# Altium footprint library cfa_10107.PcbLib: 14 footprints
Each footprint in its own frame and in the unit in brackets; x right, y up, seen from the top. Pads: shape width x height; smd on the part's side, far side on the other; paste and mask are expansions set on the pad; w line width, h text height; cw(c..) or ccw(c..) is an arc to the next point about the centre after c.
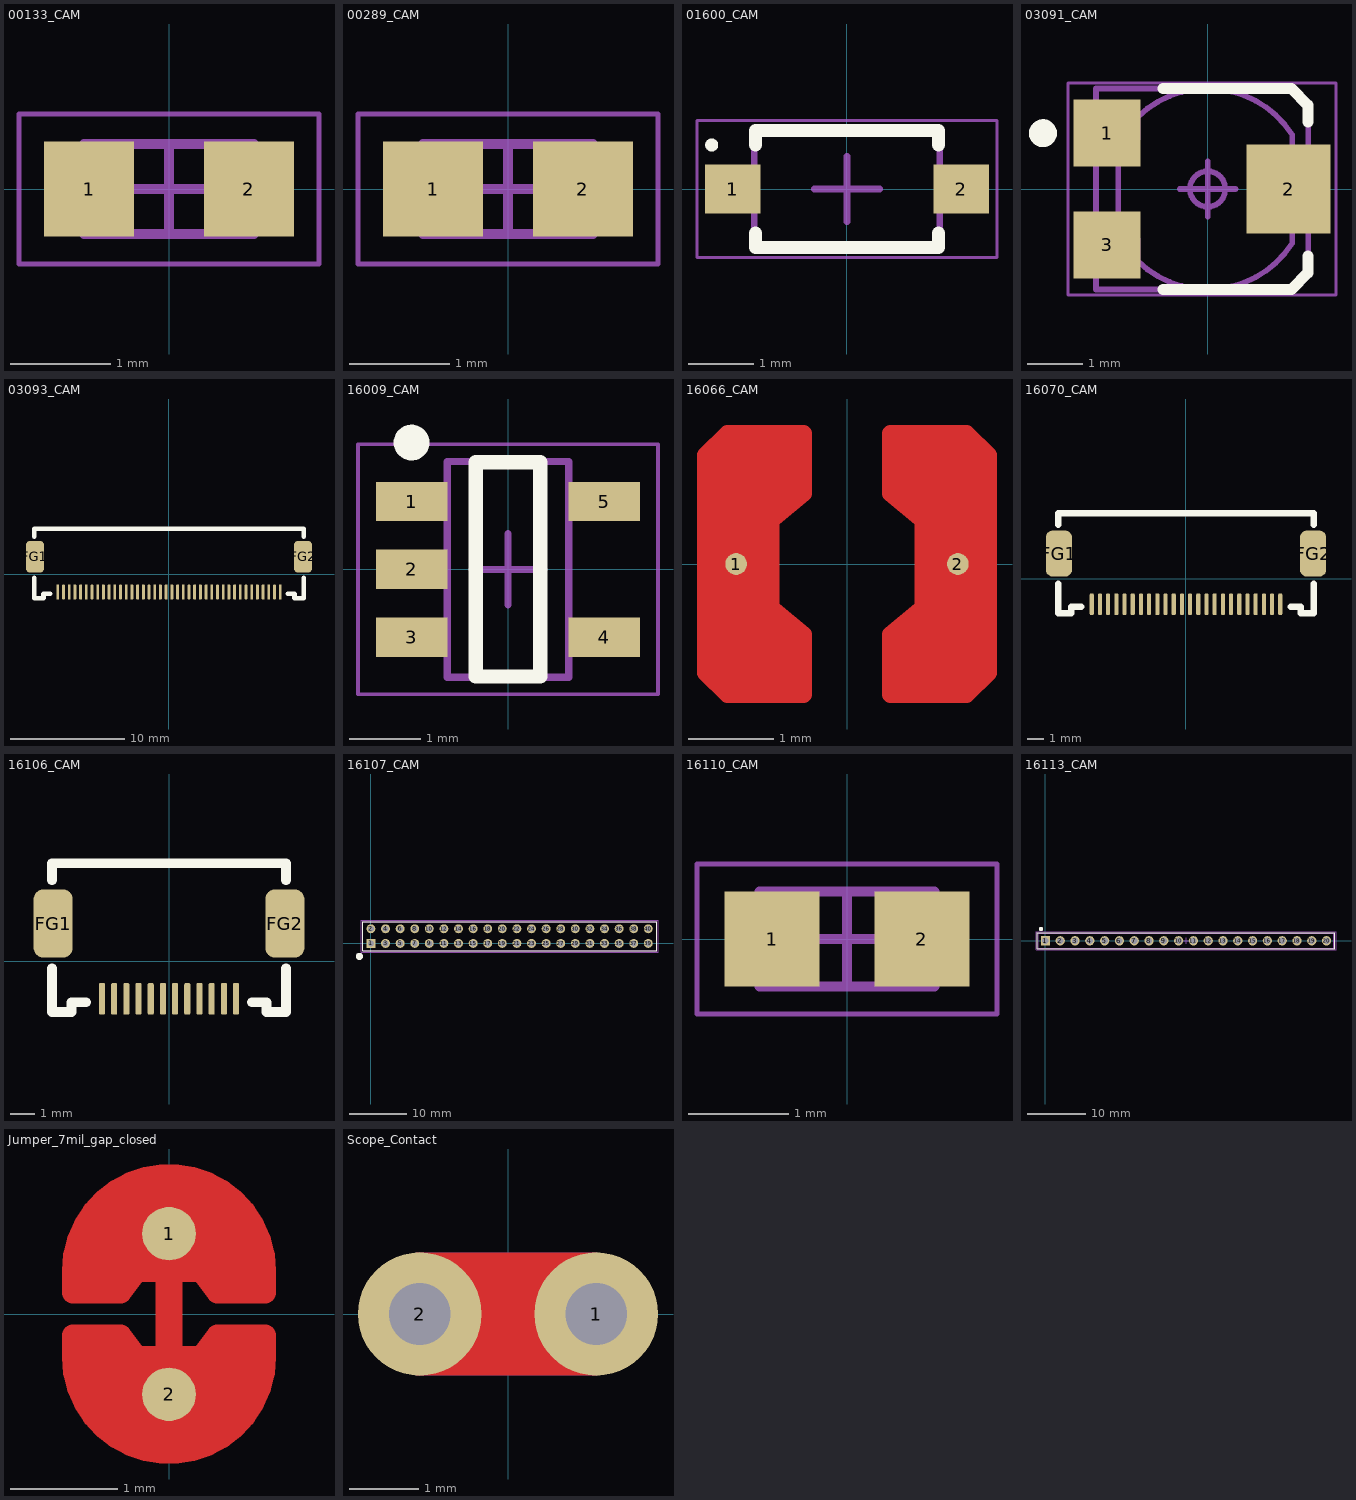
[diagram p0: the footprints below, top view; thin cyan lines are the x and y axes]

## 00133_CAM [mm] "Chip Capacitor, 2-Leads, Body 1.60x0.80mm, IPC Medium Density"
height 0.9
pads (2):
  rect 0.9x0.95 smd: 1(-0.8,0) 2(0.8,0)
Mechanical 13:
  lines w0.1: -0.85,-0.45 0.85,-0.45 0.85,0.45 -0.85,0.45 -0.85,-0.45
Mechanical 15:
  lines w0.05: -1.5,-0.75 1.5,-0.75 1.5,0.75 -1.5,0.75 -1.5,-0.75
  lines w0.1: -0.45,0 0.45,0 ; 0,-0.45 0,0.45
3D body: height 0.9, standoff 0, extent 0.55,-0.45 0.85,0.45
3D body: height 0.9, standoff 0, extent -0.85,-0.45 -0.55,0.45
3D body: height 0.9, standoff 0, extent -0.55,-0.45 0.55,0.45

## 00289_CAM [mm] "Chip Capacitor, 2-Leads, Body 1.60x0.80mm, IPC Medium Density"
height 0.9
pads (2):
  rect 1x0.95 smd: 1(-0.75,0) 2(0.75,0)
Mechanical 13:
  lines w0.1: -0.85,-0.45 -0.85,0.45 0.85,0.45 0.85,-0.45 -0.85,-0.45
Mechanical 15:
  lines w0.05: -1.5,-0.75 -1.5,0.75 1.5,0.75 1.5,-0.75 -1.5,-0.75
  lines w0.1: -0.45,0 0.45,0 ; 0,-0.45 0,0.45
3D body: height 0.9, standoff 0, extent -0.5,-0.45 0.5,0.45
3D body: height 0.9, standoff 0, extent -0.85,-0.45 -0.5,0.45
3D body: height 0.9, standoff 0, extent 0.5,-0.45 0.85,0.45

## 01600_CAM [mm] "SODFL, 2-Leads, Body 1.60x3.71mm, IPC Medium Density"
height 1.35
pads (2):
  rect 0.85x0.75 smd: 1(-1.75,0) 2(1.75,0)
Top Overlay:
  circle w0.1: c-2.075,0.675 r0.05
  lines w0.2: -1.4,-0.675 -1.4,-0.9 1.4,-0.9 1.4,-0.675 ; -1.4,0.675 -1.4,0.9 1.4,0.9 1.4,0.675
Mechanical 13:
  lines w0.1: -1.42,-0.9 -1.42,0.9 1.42,0.9 1.42,-0.9 -1.42,-0.9
Mechanical 15:
  lines w0.05: -2.3,-1.05 -2.3,1.05 2.3,1.05 2.3,-1.05 -2.3,-1.05
  lines w0.1: -0.5,0 0.5,0 ; 0,-0.5 0,0.5
3D body: height 1.35, standoff 0, extent -1.42,-0.9 1.42,0.9

## 03091_CAM [mm]
height 8.54
pads (3):
  rect 1.2x1.2 smd: 1(-1.8,1) 3(-1.8,-1)
  rect 1.5x1.6 smd: 2(1.45,0)
Top Overlay:
  circle w0.25: c-2.95,1 r0.125
  lines w0.2: -0.8,-1.8 1.5,-1.8 1.8,-1.5 1.8,-1.2 ; -0.8,1.8 1.5,1.8 1.8,1.5 1.8,1.2
Mechanical 13:
  lines w0.1: 1.515,-0.73 1.95,-0.73 1.95,-0.425 1.8,-0.425 ; 1.515,0.73 1.95,0.73 1.95,0.425 1.8,0.425 ; 1.8,-0.75 1.8,-1.5 1.5,-1.8 -2,-1.8 -2,1.8 1.5,1.8 1.8,1.5 1.8,0.75 ; 1.8,-0.42 1.8,0.42 ; -1.6,-0.895 -1.25,-0.895 -1.25,-1.295 ccw(c0,0) 1.515,-0.972 1.515,-0.352 ccw(c1.16,0) 1.515,0.352 1.515,0.972 ccw(c0,0) -1.25,1.295 -1.25,0.895 -1.6,0.895 -1.6,-0.895 ; 0,-0.318 cw(c0,0) 0,0.317 cw(c0,0) 0,-0.318
Mechanical 15:
  lines w0.05: -2.5,-1.9 2.3,-1.9 2.3,1.9 -2.5,1.9 -2.5,-1.9
  lines w0.1: -0.5,0 0.5,0 ; 0,-0.5 0,0.5
3D body "BOUR-TC33X-2.stp": height 1.15, standoff 0, extent -2,-1.8 1.963,1.8

## 03093_CAM [mm]
height 8.54
pads (42):
  rrect50% 0.25x1.3 smd: 1(-9.75,-1.545) 2(-9.25,-1.545) 3(-8.75,-1.545) 4(-8.25,-1.545) 5(-7.75,-1.545) 6(-7.25,-1.545) 7(-6.75,-1.545) 8(-6.25,-1.545) 9(-5.75,-1.545) 10(-5.25,-1.545) 11(-4.75,-1.545) 12(-4.25,-1.545) 13(-3.75,-1.545) 14(-3.25,-1.545) 15(-2.75,-1.545) 16(-2.25,-1.545) 17(-1.75,-1.545) 18(-1.25,-1.545) 19(-0.75,-1.545) 20(-0.25,-1.545) 21(0.25,-1.545) 22(0.75,-1.545) 23(1.254,-1.545) 24(1.75,-1.545) 25(2.25,-1.545) 26(2.75,-1.545) 27(3.25,-1.545) 28(3.75,-1.545) 29(4.25,-1.545) 30(4.75,-1.545) 31(5.25,-1.545) 32(5.75,-1.545) 33(6.25,-1.545) 34(6.75,-1.545) 35(7.25,-1.545) 36(7.75,-1.545) 37(8.25,-1.545) 38(8.75,-1.545) 39(9.25,-1.545) 40(9.75,-1.545)
  rrect50% 1.6x2.8 smd: FG1(-11.75,1.545) FG2(11.75,1.545)
Top Overlay:
  lines w0.4: -11.8,-0.285 -11.8,-2.085 -11,-2.085 -11,-1.685 -10.4,-1.685 ; -11.8,3.315 -11.8,4.015 ; -11.8,4.015 11.8,4.015 11.8,3.315 ; 10.4,-1.685 11,-1.685 11,-2.085 11.8,-2.085 11.8,-0.285
3D body "xf2m-4015-1a.stp": height 2, standoff 0, extent -12.05,-2.9 12.05,3

## 16009_CAM [mm] "SOT23, 5-Leads, Body 2.92x2.80mm, Pitch 0.95mm, IPC Medium Density"
height 1.45
pads (5):
  rect 1x0.55 smd: 1(-1.35,0.95) 2(-1.35,0) 3(-1.35,-0.95) 4(1.35,-0.95) 5(1.35,0.95)
Top Overlay:
  circle w0.25: c-1.35,1.775 r0.125
  lines w0.2: -0.45,-1.5 0.45,-1.5 0.45,1.5 -0.45,1.5 -0.45,-1.5
Mechanical 13:
  lines w0.1: -0.85,-1.51 -0.85,1.51 0.85,1.51 0.85,-1.51 -0.85,-1.51
Mechanical 15:
  lines w0.05: -2.1,-1.75 -2.1,1.75 2.1,1.75 2.1,-1.75 -2.1,-1.75
  lines w0.1: -0.5,0 0.5,0 ; 0,-0.5 0,0.5
3D body: height 1.45, standoff 0, extent -0.85,-1.51 0.85,1.51

## 16066_CAM [mil]
height 336.22
pads (2):
  round 10 smd: 1(-51,0) 2(51,0)
Top Layer:
  region: -55,-60 -65,-50 -65,50 -55,60 -20,60 -20,32.5 -35,20 -35,-20 -20,-32.5 -20,-60
  region: 55,-60 65,-50 65,50 55,60 20,60 20,32.5 35,20 35,-20 20,-32.5 20,-60
  lines w7.87: -65,-50 -65,50 -55,60 -20,60 -20,32.5 -35,20 -35,-20 -20,-32.5 -20,-60 -55,-60 -65,-50 ; 20,-60 20,-32.5 35,-20 35,20 20,32.5 20,60 55,60 65,50 65,-50 55,-60 20,-60
Top Solder:
  lines w7.87: -69,-52 -69,-25 -69,25 -69,52 -57,64 -16,64 -16,30.5 -31,18 -31,-18 -16,-30.5 -16,-64 -57,-64 -69,-52 ; 16,-64 57,-64 69,-52 69,-25 69,25 69,52 57,64 16,64 16,30.5 31,18 31,-18 16,-30.5 16,-64
3D body "Coilcraft-LPS3015.STEP": height 59.06, standoff 0, extent -59.64,-59.64 59.65,59.65

## 16070_CAM [mm]
height 8.54
pads (26):
  rrect50% 0.25x1.3 smd: 1(-5.75,-1.545) 2(-5.25,-1.545) 3(-4.75,-1.545) 4(-4.25,-1.545) 5(-3.75,-1.545) 6(-3.25,-1.545) 7(-2.75,-1.545) 8(-2.25,-1.545) 9(-1.75,-1.545) 10(-1.25,-1.545) 11(-0.75,-1.545) 12(-0.25,-1.545) 13(0.25,-1.545) 14(0.75,-1.545) 15(1.25,-1.545) 16(1.75,-1.545) 17(2.25,-1.545) 18(2.75,-1.545) 19(3.25,-1.545) 20(3.75,-1.545) 21(4.25,-1.545) 22(4.75,-1.545) 23(5.254,-1.545) 24(5.75,-1.545)
  rrect50% 1.6x2.8 smd: FG1(-7.75,1.545) FG2(7.75,1.545)
Top Overlay:
  lines w0.4: -7.8,-0.285 -7.8,-2.085 -7,-2.085 -7,-1.685 -6.4,-1.685 ; -7.8,3.315 -7.8,4.015 ; -7.8,4.015 7.8,4.015 7.8,3.315 ; 6.4,-1.685 7,-1.685 7,-2.085 7.8,-2.085 7.8,-0.285

## 16106_CAM [mm]
height 8.54
pads (14):
  rrect50% 0.25x1.3 smd: 1(-2.75,-1.545) 2(-2.25,-1.545) 3(-1.75,-1.545) 4(-1.25,-1.545) 5(-0.75,-1.545) 6(-0.25,-1.545) 7(0.25,-1.545) 8(0.75,-1.545) 9(1.25,-1.545) 10(1.75,-1.545) 11(2.254,-1.545) 12(2.75,-1.545)
  rrect50% 1.6x2.8 smd: FG1(-4.75,1.545) FG2(4.75,1.545)
Top Overlay:
  lines w0.4: -4.8,-0.285 -4.8,-2.085 -4,-2.085 -4,-1.685 -3.4,-1.685 ; -4.8,3.315 -4.8,4.015 ; -4.7,4.015 4.8,4.015 4.8,3.315 ; 3.4,-1.685 4,-1.685 4,-2.085 4.8,-2.085 4.8,-0.285

## 16107_CAM [mm]
height 8.54
pads (40):
  rect 1.55x1.55 hole 1.02: 1(0,0)
  round 1.55 hole 1.02: 2(0,2.54) 3(2.54,0) 4(2.54,2.54) 5(5.08,0) 6(5.08,2.54) 7(7.62,0) 8(7.62,2.54) 9(10.16,0) 10(10.16,2.54) 11(12.7,0) 12(12.7,2.54) 13(15.24,0) 14(15.24,2.54) 15(17.78,0) 16(17.78,2.54) 17(20.32,0) 18(20.32,2.54) 19(22.86,0) 20(22.86,2.54) 21(25.4,0) 22(25.4,2.54) 23(27.94,0) 24(27.94,2.54) 25(30.48,0) 26(30.48,2.54) 27(33.02,0) 28(33.02,2.54) 29(35.56,0) 30(35.56,2.54) 31(38.1,0) 32(38.1,2.54) 33(40.64,0) 34(40.64,2.54) 35(43.18,0) 36(43.18,2.54) 37(45.72,0) 38(45.72,2.54) 39(48.26,0) 40(48.26,2.54)
Top Overlay:
  circle w0.75: c-2,-2.25 r0.25
  lines w0.2: -1.46,-1.27 -1.46,3.81 49.72,3.81 49.72,-1.27 -1.46,-1.27
Mechanical 13:
  lines w0.1: -1.46,-1.27 -1.46,3.81 49.72,3.81 49.72,-1.27 -1.46,-1.27
Mechanical 15:
  lines w0.05: -1.685,-1.495 -1.685,4.035 49.945,4.035 49.945,-1.495 -1.685,-1.495
3D body "TSW-120-24-X-D.step": height 9.27, standoff -2.92, extent -1.27,-1.27 49.53,3.81

## 16110_CAM [mm] "Chip Resistor, 2-Leads, Body 1.60x0.85mm, IPC Medium Density"
height 0.55
pads (2):
  rect 0.95x0.95 smd: 1(-0.75,0) 2(0.75,0)
Mechanical 13:
  lines w0.1: -0.875,-0.475 -0.875,0.475 0.875,0.475 0.875,-0.475 -0.875,-0.475
Mechanical 15:
  lines w0.05: -1.5,-0.75 -1.5,0.75 1.5,0.75 1.5,-0.75 -1.5,-0.75
  lines w0.1: -0.475,0 0.475,0 ; 0,-0.475 0,0.475
3D body: height 0.55, standoff 0, extent -0.575,-0.475 0.575,0.475
3D body: height 0.55, standoff 0, extent -0.875,-0.475 -0.575,0.475
3D body: height 0.55, standoff 0, extent 0.575,-0.475 0.875,0.475

## 16113_CAM [mm]
height 8.54
pads (20):
  rect 1.6x1.6 hole 1.1: 1(0,0)
  round 1.6 hole 1.1: 2(2.54,0) 3(5.08,0) 4(7.62,0) 5(10.16,0) 6(12.7,0) 7(15.24,0) 8(17.78,0) 9(20.32,0) 10(22.86,0) 11(25.4,0) 12(27.94,0) 13(30.48,0) 14(33.02,0) 15(35.56,0) 16(38.1,0) 17(40.64,0) 18(43.18,0) 19(45.72,0) 20(48.26,0)
Top Overlay:
  circle w0.5: c-0.762,2.032 r0.125
  lines w0.2: -1.42,-1.345 -1.42,1.345 49.68,1.345 49.68,-1.345 -1.42,-1.345
Mechanical 13:
  lines w0.1: -1.27,-1.27 -1.27,1.27 49.53,1.27 49.53,-1.27 -1.27,-1.27
Mechanical 15:
  lines w0.05: 23.63,0 24.63,0 ; 24.13,-0.5 24.13,0.5 ; -1.62,-1.545 49.88,-1.545 49.88,1.545 -1.62,1.545 -1.62,-1.545
3D body "61302011121.stp": height 8.57, standoff -2.97, extent -1.27,-1.27 49.53,1.27

## Jumper_7mil_gap_closed [mm]
height 8.54
pads (2):
  round 0.5 smd paste+0 mask+0: 1(0,0.75) 2(0,-0.75)
Top Layer:
  region: -0.9,0.2 -0.9,0.4 -0.9,0.518 -0.839,0.747 -0.72,0.953 -0.553,1.12 -0.347,1.239 -0.118,1.3 0.118,1.3 0.347,1.239 0.553,1.12 0.72,0.953 0.839,0.747 0.9,0.518 0.9,0.4 0.9,0.2 0.45,0.2 0.3,0.4 -0.3,0.4 -0.45,0.2
  region: -0.9,-0.2 -0.9,-0.4 -0.9,-0.518 -0.839,-0.747 -0.72,-0.953 -0.553,-1.12 -0.347,-1.239 -0.118,-1.3 0.118,-1.3 0.347,-1.239 0.553,-1.12 0.72,-0.953 0.839,-0.747 0.9,-0.518 0.9,-0.4 0.9,-0.2 0.45,-0.2 0.3,-0.4 -0.3,-0.4 -0.45,-0.2
  lines w0.2: -0.9,-0.4 ccw(c0,-0.4) 0.9,-0.4 0.9,-0.2 0.45,-0.2 0.3,-0.4 0,-0.4 -0.3,-0.4 -0.45,-0.2 -0.9,-0.2 -0.9,-0.4 ; -0.9,0.2 -0.9,0.4 cw(c0,0.4) 0.9,0.4 0.9,0.2 0.45,0.2 0.3,0.4 0,0.4 -0.3,0.4 -0.45,0.2 -0.9,0.2
  lines w0.25: 0,-0.4 0,0.4
Top Solder:
  region: -1,-0.4 -1,-0.532 -0.932,-0.786 -0.8,-1.014 -0.614,-1.2 -0.386,-1.332 -0.132,-1.4 0.132,-1.4 0.386,-1.332 0.614,-1.2 0.8,-1.014 0.932,-0.786 1,-0.532 1,-0.4 1,0.4 1,0.532 0.932,0.786 0.8,1.014 0.614,1.2 0.386,1.332 0.132,1.4 -0.132,1.4 -0.386,1.332 -0.614,1.2 -0.8,1.014 -0.932,0.786 -1,0.532 -1,0.4
  lines w0.2: -1,-0.4 ccw(c0,-0.4) 1,-0.4 1,0.4 ccw(c0,0.4) -1,0.4 -1,-0.4

## Scope_Contact [mil]
height 336.22
pads (2):
  round 70 hole 35: 1(50,0) 2(-50,0)
Top Layer:
  region: -51,-31 50,-31 50,31 -51,31
  lines w7.87: -51,-31 50,-31 50,31 -51,31 -51,-31
Bottom Layer:
  region: -52,-31 49,-31 49,31 -52,31
  lines w7.87: -52,-31 49,-31 49,31 -52,31 -52,-31
Top Solder:
  region: -51,35 50,35 50,-35 -50,-35 -50,35
  lines w7.87: -51,35 -50,35 -50,-35 50,-35 50,35 -51,35
Bottom Solder:
  region: -49,35 52,35 52,-35 -48,-35 -48,35
  lines w7.87: -48,-35 52,-35 52,35 -48,35 -48,-35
